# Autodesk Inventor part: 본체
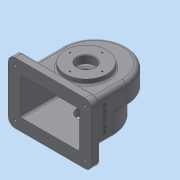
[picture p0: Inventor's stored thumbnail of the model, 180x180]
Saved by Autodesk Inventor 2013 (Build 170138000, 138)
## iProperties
Created: 2017-11
Part Number: 본체
Material: 일반
Document SubType Name: Modeling
Designer: dgall
Density: 1 g/cm^3
Author: dgall
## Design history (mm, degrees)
sketch "스케치1"
  geometry: L1 (-58, 0)-(-58, -80); L2 (-58, -80)-(58, -80); L3 (58, -80)-(58, 0); A1 r 58 centre (0, 0) between (-58, 0) and (58, 0); 1 further point
  constraints: 6 end point, 2 point on circle, 2 tangent, 2 vertical, 1 centre point, 1 coincident, 1 perpendicular
  dimensions: "d0" = 58 radius of A1; "d1" = 80 distance of L1.start L1.end
extrude "돌출1" new body sketch "스케치1" distance "d2" = 38; taper "d3" = 0 deg
sketch "스케치2"
  geometry: L1 (58, 0)-(58, -80) reference; L2 (-58, -80)-(-58, 0) reference; L3 (58, -80)-(-58, -80) reference; L4 (-58, -23)-(-58, -80); L5 (58, -80)-(-58, -80); L6 (58, -80)-(58, -23); A1 r 58 centre (0, 0) between (58, 0) and (-58, 0) reference; A2 r 58 centre (0, -23) between (10.724, -80) and (-10.724, -80)
  constraints: 6 end point, 4 point on circle, 4 point on line, 2 collinear, 1 centre point, 1 vertical alignment
  dimensions: "d4" = 58 radius of A2; "d5" = 57 distance from line of L3 A2.centre
extrude "돌출2" join sketch "스케치2" distance "d6" = 38; taper "d7" = 0 deg
feature "쉘1" dims "d8" = 5
sketch "스케치3"
  geometry: L1 (-58, -80)-(58, -80) reference; C1 r 37.5 at (0, -15); A1 r 58 centre (0, 0) between (58, 0) and (-58, 0) reference
  constraints: 1 centre point, 1 vertical alignment
  dimensions: "d9" = 75 diameter of C1; "d10" = 65 distance from line of L1 C1.centre
extrude "돌출3" join sketch "스케치3" distance "d11" = 9; taper "d12" = 0 deg
sketch "스케치4"
  geometry: L1 (-58, -80)-(58, -80) reference; C1 r 31 at (0, -15); A1 r 58 centre (0, -23) between (58, -23) and (-58, -23) reference; 1 further point
  constraints: 1 centre point, 1 vertical alignment
  dimensions: "d13" = 62 diameter of C1; "d14" = 65 distance from line of L1 C1.centre
extrude "돌출4" join sketch "스케치4" distance "d15" = 10; taper "d16" = 0 deg
sketch "스케치5"
  geometry: C1 r 37.5 at (0, 0) reference; C2 r 16 at (0, 0); 1 further point
  constraints: 1 centre point, 1 coincident
  dimensions: "d17" = 32 diameter of C2
extrude "돌출5" cut sketch "스케치5" stored distance "d18" = 10; taper "d19" = 0 deg
sketch "스케치6" dims "d20" = 58
  geometry: C1 r 37.5 at (0, 0) reference; 3 further points
  constraints: 2 vertical alignment, 1 coincident, 2 other
hole "구멍1" sketch "스케치6" at (0, 29) diameter "d21" = 2.459; stored, may be unused: countersink angle "d25" = 90 deg, drill point angle "d27" = 118 deg; dims "d22" = 6, "d23" = 4, "d24" = 2, "d26" = 8
sketch "스케치7" dims "d31" = 52
  geometry: C1 r 16 at (0, 0) reference; C2 r 31 at (0, 0) reference; 3 further points
  constraints: 2 vertical alignment, 1 coincident, 2 other
hole "구멍2" sketch "스케치7" at (0, 26) diameter "d32" = 2.459; stored, may be unused: countersink angle "d36" = 90 deg, drill point angle "d38" = 118 deg; dims "d33" = 6, "d34" = 4, "d35" = 2, "d37" = 8
chamfer "모따기1" distance "d42" = 1; stored, may be unused: second distance "d43" = 2, angle "d44" = 45 deg
sketch "스케치8"
  geometry: L1 (-17, 17)-(133, 17); L2 (133, 17)-(133, -93); L3 (133, -93)-(-17, -93); L4 (-17, -93)-(-17, 17); L5 (116, -38)-(0, -38) reference; L6 (0, 0)-(116, 0); L7 (116, 0)-(116, -76); L8 (116, -76)-(0, -76); L9 (0, -76)-(0, 0); 4 further points
  constraints: 16 end point, 4 parallel, 3 midpoint, 2 horizontal, 2 perpendicular, 1 horizontal alignment, 1 vertical alignment
  dimensions: "d45" = 150 distance of L1.start L1.end; "d47" = 110 distance of L1.end L2.end
extrude "돌출6" join sketch "스케치8" distance "d48" = 15; taper "d49" = 0 deg
fillet "모깎기1" dims "d50" = 12
sketch "스케치9"
  geometry: A1 r 12 centre (-5, -5) between (-17, -5) and (-5, -17) reference; A2 r 12 centre (121, -5) between (121, -17) and (133, -5) reference; A3 r 12 centre (121, 81) between (133, 81) and (121, 93) reference; A4 r 12 centre (-5, 81) between (-5, 93) and (-17, 81) reference; 5 further points
  constraints: 4 coincident
hole "구멍3" sketch "스케치9" at (-5, 81), (-5, -5), (121, -5), (121, 81) diameter "d51" = 5; stored, may be unused: countersink angle "d55" = 90 deg, drill point angle "d57" = 118 deg; dims "d52" = 6, "d53" = 12, "d54" = 5, "d56" = 8
node "작업 평면1"
sketch "스케치11"
  geometry: L1 (-121, 55)-(-121, 93) reference; L2 (-121, 55)-(-5, 55) reference; L3 (-5, 55)-(-5, 93) reference; L4 (-121, 93)-(-5, 93) reference; L5 (12, 12)-(12, 98) reference; C1 r 6 at (-63, 74); 2 further points
  constraints: 1 centre point, 1 horizontal alignment, 1 midpoint
  dimensions: "d59" = 12 diameter of C1; "d60" = 75 distance from line of C1.centre L5
extrude "돌출7" join sketch "스케치11" stored distance "d61" = 15; taper "d62" = 0 deg
hole "구멍4" diameter "d65" = 4.459; stored, may be unused: countersink angle "d69" = 90 deg, drill point angle "d71" = 118 deg; dims "d63" = 10, "d64" = 10, "d66" = 6, "d67" = 12, "d68" = 5, "d70" = 8
fillet "모깎기2" dims "d72" = 8
fillet "모깎기3" dims "d73" = 3
fillet "모깎기4" dims "d74" = 3
fillet "모깎기5" dims "d75" = 3
fillet "모깎기6" dims "d76" = 3
fillet "모깎기7" dims "d77" = 3
fillet "모깎기8" dims "d78" = 3
sketch "스케치12"
  geometry: L1 (-40, -57)-(46, -57) reference; L2 (-35, 23)-(-35, -39) reference; 2 further points
  constraints: 1 other
  dimensions: "d79" = 40 distance from line of L1 point (3, -17); "d80" = 38 distance from line of L2 point (3, -17)
feature "엠보싱1" sketch "스케치12" dims "d0" = 58, "d1" = 80, "d81" = 0.5, "d82" = 0
node "솔리드1"
pattern_circular "원형 패턴1" dims angle "d29" = 360 deg
pattern_circular "원형 패턴2" dims angle "d40" = 360 deg
node "투영된 루프1"
other parameters: "d58" = -144
